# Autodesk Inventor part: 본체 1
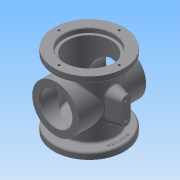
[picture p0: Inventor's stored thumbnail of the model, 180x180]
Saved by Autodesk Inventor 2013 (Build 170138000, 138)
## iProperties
Created: 2018-02
Part Number: 본체 1
Material: 일반
Document SubType Name: Modeling
Designer: Administrator
Density: 1 g/cm^3
Author: Administrator
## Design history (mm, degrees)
sketch "스케치1"
  geometry: C1 r 37 at (0, 0); 1 further point
  constraints: 1 centre point, 1 coincident
  dimensions: "d0" = 74 diameter of C1
extrude "돌출1" new body sketch "스케치1" stored distance "d1" = 108; taper "d2" = 0 deg
sketch "스케치2"
  geometry: C1 r 37 at (0, 0) reference; C2 r 52.5 at (0, 0)
  constraints: 1 centre point, 1 coincident
  dimensions: "d3" = 105 diameter of C2
extrude "돌출2" join sketch "스케치2" distance "d4" = 10; taper "d5" = 0 deg
node "작업 평면1"
sketch "스케치3"
  geometry: C1 r 35 at (0, 0); 1 further point
  constraints: 1 centre point, 1 coincident
  dimensions: "d7" = 70 diameter of C1
extrude "돌출3" join sketch "스케치3" stored distance "d8" = 10; taper "d9" = 0 deg
sketch "스케치4"
  geometry: C1 r 52.5 at (0, 0) reference; C2 r 33 at (0, 0)
  constraints: 1 centre point, 1 coincident
  dimensions: "d10" = 66 diameter of C2
extrude "돌출4" cut sketch "스케치4" distance "d11" = 86; taper "d12" = 0 deg
sketch "스케치5"
  geometry: C1 r 33 at (0, 0) reference; C2 r 52.5 at (0, 0) reference; C3 r 37 at (0, 0)
  constraints: 1 centre point, 1 coincident
  dimensions: "d13" = 74 diameter of C3
extrude "돌출5" cut sketch "스케치5" distance "d14" = 7; taper "d15" = 0 deg
sketch "스케치6"
  geometry: C1 r 52.5 at (0, 0) reference; C2 r 34 at (0, 0)
  constraints: 1 centre point, 1 coincident
  dimensions: "d16" = 68 diameter of C2
extrude "돌출6" cut sketch "스케치6" distance "d17" = 16; taper "d18" = 0 deg
sketch "스케치7"
  geometry: C1 r 35 at (0, 0) reference; C2 r 24 at (0, 0)
  constraints: 1 centre point, 1 coincident
  dimensions: "d19" = 48 diameter of C2
extrude "돌출7" cut sketch "스케치7" stored distance "d20" = 16; taper "d21" = 0 deg
sketch "스케치8"
  geometry: C1 r 24 at (0, 0) reference; 1 further point
  constraints: 1 vertical alignment
  dimensions: "d22" = 29 distance of C1.centre point (0, 29)
hole "구멍1" sketch "스케치8" at (0, 29) diameter "d23" = 3.242; stored, may be unused: countersink angle "d27" = 90 deg, drill point angle "d29" = 118 deg; dims "d24" = 4, "d25" = 4, "d26" = 2, "d28" = 6
sketch "스케치9"
  geometry: C1 r 37 at (0, 0) reference; 1 further point
  constraints: 1 vertical alignment
  dimensions: "d33" = 45 distance of C1.centre point (0, 45)
hole "구멍2" sketch "스케치9" at (0, 45) diameter "d34" = 3.242; stored, may be unused: countersink angle "d38" = 90 deg, drill point angle "d40" = 118 deg; dims "d35" = 4, "d36" = 4, "d37" = 2, "d39" = 6
node "작업 평면2"
sketch "스케치11"
  geometry: L1 (7, 13)-(7, -13); L2 (-7, 13)-(-7, -13); A1 r 7 centre (0, 13) between (7, 13) and (-7, 13); A2 r 7 centre (0, -13) between (-7, -13) and (7, -13); 2 further points
  constraints: 4 end point, 4 point on circle, 3 tangent, 2 centre point, 2 vertical alignment, 1 horizontal alignment, 1 midpoint, 1 parallel
  dimensions: "d54" = 14 diameter of A1; "d56" = 14 diameter of A2; "d97" = 40 dimension on A2 A1
extrude "돌출8" join sketch "스케치11" stored distance "d58" = 16; taper "d59" = 15 deg
sketch "스케치13"
  geometry: C1 r 34 at (0, 0) reference; C2 r 5 at (0, 0)
  constraints: 1 centre point, 1 coincident
  dimensions: "d69" = 10 diameter of C2
extrude "돌출9" cut sketch "스케치13" distance "d70" = 16; taper "d71" = 0 deg
fillet "모깎기2" dims "d72" = 3
sketch "스케치14"
  geometry: C1 r 49.5 at (0, 0) reference; C2 r 43 at (0, 0)
  constraints: 1 centre point, 1 coincident, 1 other
  dimensions: "d73" = 86 diameter of C2
feature "엠보싱1" sketch "스케치14" dims "d74" = 0.5, "d75" = 0
fillet "모깎기6" dims "d79" = 3
fillet "모깎기7" dims "d80" = 3
fillet "모깎기8" dims "d81" = 3
chamfer "모따기1" distance "d82" = 1; stored, may be unused: second distance "d83" = 2, angle "d84" = 45 deg
chamfer "모따기2" distance "d85" = 1; stored, may be unused: second distance "d86" = 2, angle "d87" = 45 deg
fillet "모깎기9" dims "d88" = 3
fillet "모깎기10" dims "d89" = 3
sketch "스케치15"
  geometry: A1 r 7 centre (-13, 0) between (-13, 7) and (-13, -7) reference; A2 r 7 centre (13, 0) between (13, -7) and (13, 7) reference; 3 further points
  constraints: 2 coincident
hole "구멍4" sketch "스케치15" at (-13, 0), (13, 0) diameter "d90" = 4.134; stored, may be unused: countersink angle "d94" = 90 deg, drill point angle "d96" = 118 deg; dims "d91" = 6, "d92" = 4, "d93" = 2, "d95" = 8
chamfer "모따기3" distance "d98" = 1; stored, may be unused: second distance "d99" = 2, angle "d100" = 45 deg
fillet "모깎기11" dims "d101" = 3
node "솔리드1"
mirror "대칭1"
mirror "대칭2"
pattern_circular "원형 패턴1" dims angle "d31" = 360 deg
pattern_circular "원형 패턴2" dims angle "d42" = 360 deg
mirror "대칭3"
other parameters: "d52" = 55
